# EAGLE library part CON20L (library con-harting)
CONNECTOR
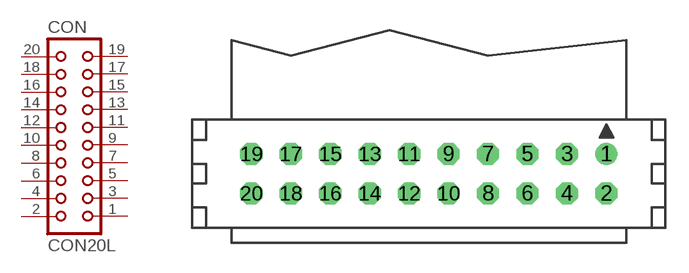
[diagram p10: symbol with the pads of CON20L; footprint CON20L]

Designator prefix CON

## CON20L (OC_FARNELL: unknown; OC_NEWARK: unknown)  [CON20L]
1  1  pas
2  2  pas
3  3  pas
4  4  pas
5  5  pas
6  6  pas
7  7  pas
8  8  pas
9  9  pas
10  10  pas
11  11  pas
12  12  pas
13  13  pas
14  14  pas
15  15  pas
16  16  pas
17  17  pas
18  18  pas
19  19  pas
20  20  pas

## Footprint CON20L (pad centres in mm)
CONNECTOR
drill 0.914 round: 1 11.43,1.27
drill 0.914 octagon: 2 11.43,-1.27; 3 8.89,1.27; 4 8.89,-1.27; 5 6.35,1.27; 6 6.35,-1.27; 7 3.81,1.27; 8 3.81,-1.27; 9 1.27,1.27; 10 1.27,-1.27; 11 -1.27,1.27; 12 -1.27,-1.27; 13 -3.81,1.27; 14 -3.81,-1.27; 15 -6.35,1.27; 16 -6.35,-1.27; 17 -8.89,1.27; 18 -8.89,-1.27; 19 -11.43,1.27; 20 -11.43,-1.27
